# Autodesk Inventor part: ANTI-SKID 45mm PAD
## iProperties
Created: 2007-03
Part Number: ANTI-SKID 45mm PAD
Material: Rubber
Document SubType Name: Modeling
Designer: Andy Moles
Mass: 6.20162 g
Surface Area: 30.2508 cm^2
Volume: 6.66841 cm^3
Density: 0.93 g/cm^3
Author: Andy Moles
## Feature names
1. Extrusion1
2. Extrusion2
3. Fillet1
